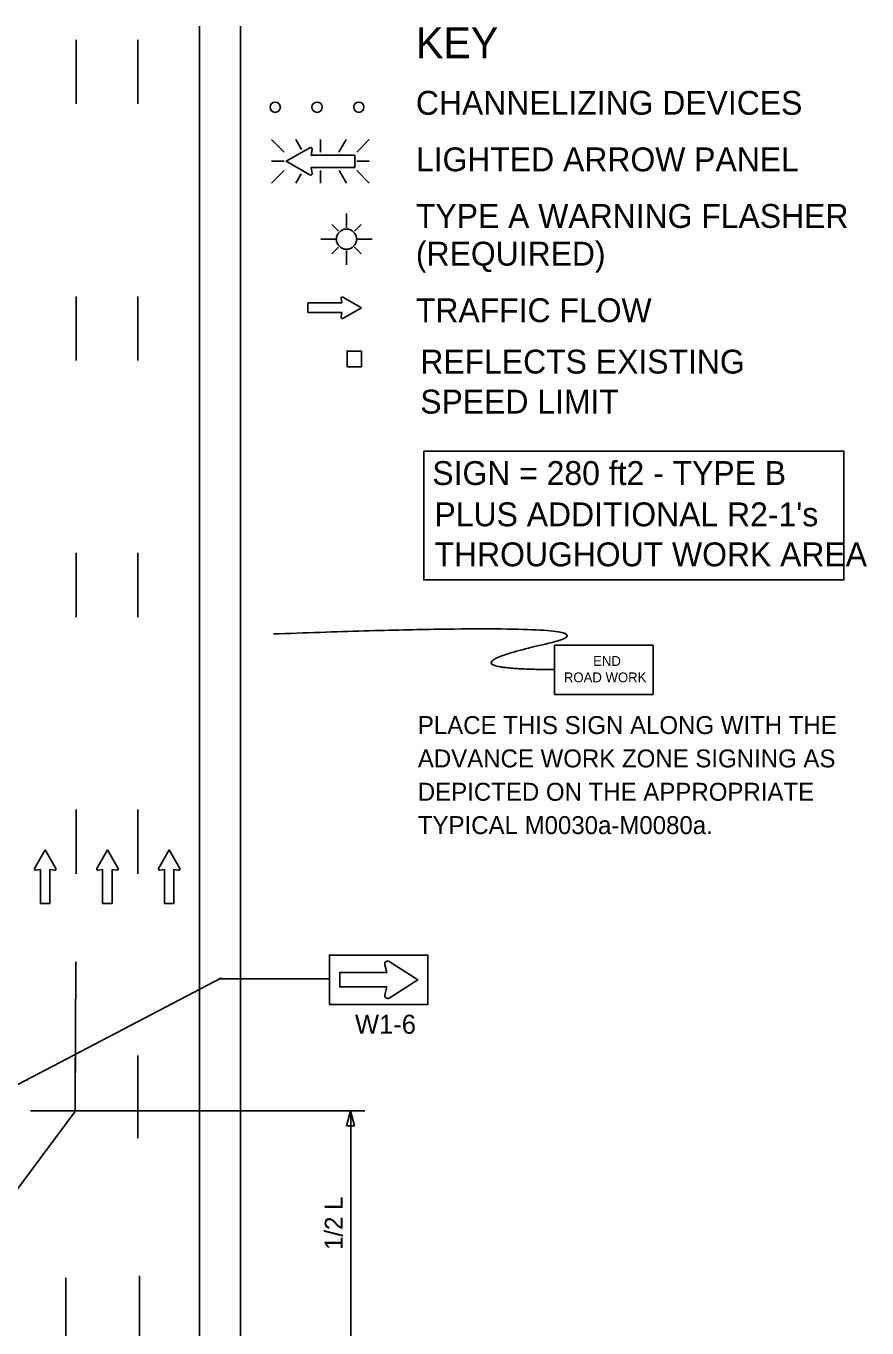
# Model space of a CAD drawing. Extents: x 16038 to 19504, y 5920 to 8321.
# Drawn here: x 17087 to 17415, y 7704 to 8212 of the extents above; entities that cross this region are included whole.
import ezdxf

# ---------------------------------------------------------------- set-up
doc = ezdxf.new("R2010")
doc.units = 0
for name, color, linetype in [('ALI_LEGAL_EX', 7, 'Continuous'), ('MT_SCRATCH_LEVEL_E', 7, 'Continuous'), ('PAVT_EDGE_EX', 7, 'Continuous'), ('TRAFFIC_SIGNS_PR', 7, 'Continuous'), ('TYPICAL_TEXT_DIMEN_EX', 7, 'Continuous'), ('TYPICAL_TEXT_DIMEN_PR', 7, 'Continuous')]:
    doc.layers.add(name, color=color, linetype=linetype)

msp = doc.modelspace()

# ---------------------------------------------------------------- linework, layer by layer
at = {"layer": 'ALI_LEGAL_EX'}
for points in [[(17106.3, 8181.21), (17106.3, 8206.21)], [(17130.3, 8181.21), (17130.3, 8206.21)], [(17106.3, 8081.21), (17106.3, 8106.21)], [(17130.3, 8081.21), (17130.3, 8106.21)], [(17106.3, 7981.21), (17106.3, 8006.21)], [(17130.3, 7981.21), (17130.3, 8006.21)], [(17106.3, 7881.21), (17106.3, 7906.21)], [(17130.3, 7881.21), (17130.3, 7906.21)], [(17130.3, 7778.16), (17130.3, 7810.35)], [(17105.83, 7788.97), (17105.83, 7809.49)], [(17102.22, 7691.46), (17102.22, 7723.64)], [(17130.99, 7692.31), (17130.99, 7724.5)]]:
    msp.add_lwpolyline(points, dxfattribs=at)
at = {"layer": 'MT_SCRATCH_LEVEL_E'}
for p, q in [((17209.56, 8105.43), (17209.88, 8103.65)), ((17209.56, 8105.43), (17209.88, 8103.65)), ((17217.49, 8101.8), (17210.25, 8105.91)), ((17217.49, 8101.8), (17210.25, 8105.91)), ((17209.88, 8103.65), (17196.62, 8103.65)), ((17196.62, 8103.65), (17196.62, 8099.91)), ((17209.88, 8103.65), (17196.62, 8103.65)), ((17196.62, 8103.65), (17196.62, 8099.91)), ((17196.62, 8099.91), (17209.88, 8099.91)), ((17196.62, 8099.91), (17209.88, 8099.91)), ((17209.88, 8099.91), (17209.56, 8098.13)), ((17209.88, 8099.91), (17209.56, 8098.13)), ((17210.25, 8097.65), (17217.49, 8101.8)), ((17210.25, 8097.65), (17217.49, 8101.8)), ((17094.17, 7890.46), (17090.06, 7883.22)), ((17094.17, 7890.46), (17090.06, 7883.22)), ((17098.32, 7883.22), (17094.17, 7890.46)), ((17098.32, 7883.22), (17094.17, 7890.46)), ((17118.44, 7890.46), (17114.33, 7883.22)), ((17118.44, 7890.46), (17114.33, 7883.22)), ((17122.59, 7883.22), (17118.44, 7890.46)), ((17122.59, 7883.22), (17118.44, 7890.46)), ((17142.51, 7890.46), (17138.4, 7883.22)), ((17142.51, 7890.46), (17138.4, 7883.22)), ((17146.66, 7883.22), (17142.51, 7890.46)), ((17146.66, 7883.22), (17142.51, 7890.46)), ((17090.54, 7882.54), (17092.32, 7882.85)), ((17090.54, 7882.54), (17092.32, 7882.85)), ((17092.32, 7882.85), (17092.32, 7869.6)), ((17092.32, 7882.85), (17092.32, 7869.6)), ((17096.06, 7869.6), (17096.06, 7882.85)), ((17096.06, 7882.85), (17097.84, 7882.54)), ((17096.06, 7869.6), (17096.06, 7882.85)), ((17096.06, 7882.85), (17097.84, 7882.54)), ((17114.81, 7882.54), (17116.59, 7882.85)), ((17114.81, 7882.54), (17116.59, 7882.85)), ((17116.59, 7882.85), (17116.59, 7869.6)), ((17116.59, 7882.85), (17116.59, 7869.6)), ((17120.33, 7869.6), (17120.33, 7882.85)), ((17120.33, 7882.85), (17122.11, 7882.54)), ((17120.33, 7869.6), (17120.33, 7882.85)), ((17120.33, 7882.85), (17122.11, 7882.54)), ((17138.88, 7882.54), (17140.66, 7882.85)), ((17138.88, 7882.54), (17140.66, 7882.85)), ((17140.66, 7882.85), (17140.66, 7869.6)), ((17140.66, 7882.85), (17140.66, 7869.6)), ((17144.4, 7869.6), (17144.4, 7882.85)), ((17144.4, 7882.85), (17146.18, 7882.54)), ((17144.4, 7869.6), (17144.4, 7882.85)), ((17144.4, 7882.85), (17146.18, 7882.54)), ((17092.32, 7869.6), (17096.06, 7869.6)), ((17092.32, 7869.6), (17096.06, 7869.6)), ((17116.59, 7869.6), (17120.33, 7869.6)), ((17116.59, 7869.6), (17120.33, 7869.6)), ((17140.66, 7869.6), (17144.4, 7869.6)), ((17140.66, 7869.6), (17144.4, 7869.6))]:
    msp.add_line(p, q, dxfattribs=at)
for centre, start, end in [((17210.02, 8105.5), 60.4248, 189.9638), ((17210.02, 8105.5), 60.4248, 189.9638), ((17210.02, 8098.06), 170.0362, 299.7731), ((17210.02, 8098.06), 170.0362, 299.7731), ((17090.47, 7883), 150.4248, 279.9638), ((17090.47, 7883), 150.4248, 279.9638), ((17097.91, 7883), 260.0362, 29.7731), ((17097.91, 7883), 260.0362, 29.7731), ((17114.74, 7883), 150.4248, 279.9638), ((17114.74, 7883), 150.4248, 279.9638), ((17122.18, 7883), 260.0362, 29.7731), ((17122.18, 7883), 260.0362, 29.7731), ((17138.81, 7883), 150.4248, 279.9638), ((17138.81, 7883), 150.4248, 279.9638), ((17146.25, 7883), 260.0362, 29.7731), ((17146.25, 7883), 260.0362, 29.7731)]:
    msp.add_arc(centre, 0.463, start, end, dxfattribs=at)
at = {"layer": 'PAVT_EDGE_EX'}
for p, q in [((17154.3, 8211.6), (17154.3, 7367.79)), ((17170.3, 8211.6), (17170.3, 7367.79))]:
    msp.add_line(p, q, dxfattribs=at)
at = {"layer": 'TRAFFIC_SIGNS_PR'}
for p, q in [((17182.37, 8167.35), (17187.31, 8162.42)), ((17194.14, 8163.53), (17191.93, 8167.36)), ((17201.46, 8162.42), (17201.46, 8167.36)), ((17208.69, 8162.42), (17211.54, 8167.36)), ((17215.61, 8162.42), (17220.54, 8167.36)), ((17187.31, 8158.87), (17182.37, 8158.87)), ((17182.37, 8150.38), (17187.31, 8155.31)), ((17201.46, 8155.31), (17201.46, 8150.38)), ((17211.59, 8150.38), (17208.74, 8155.31)), ((17215.61, 8158.87), (17220.54, 8158.87)), ((17215.61, 8155.31), (17220.54, 8150.37)), ((17191.89, 8150.38), (17194, 8154.04)), ((17211.64, 8132.95), (17211.64, 8138.58)), ((17208.5, 8131.65), (17205.87, 8134.29)), ((17214.78, 8131.65), (17217.41, 8134.29)), ((17207.7, 8128.52), (17201.66, 8128.52)), ((17208.5, 8125.38), (17205.87, 8122.75)), ((17214.78, 8125.38), (17217.41, 8122.75)), ((17215.58, 8128.52), (17221.67, 8128.52)), ((17211.64, 8118.57), (17211.64, 8124.08)), ((17227.41, 7842.65), (17226.57, 7845.71)), ((17228.25, 7846.95), (17239.41, 7839.85)), ((17162.88, 7840.66), (17010.11, 7760.54)), ((17209.01, 7842.65), (17227.41, 7842.65)), ((17209.01, 7842.65), (17209.01, 7837.05)), ((17227.41, 7837.05), (17209.01, 7837.05)), ((17226.57, 7833.99), (17227.41, 7837.05)), ((17239.41, 7839.85), (17228.25, 7832.75))]:
    msp.add_line(p, q, dxfattribs=at)
for points in [[(17197.38, 8164.14), (17188.09, 8158.87), (17197.39, 8153.54)], [(17198.26, 8154.17), (17197.86, 8156.44), (17214.87, 8156.44), (17214.87, 8161.24), (17197.86, 8161.24), (17198.26, 8163.52)], [(17226.57, 7845.71), (17227.41, 7842.65), (17209.01, 7842.65), (17209.01, 7837.05), (17227.41, 7837.05), (17226.57, 7833.99)], [(17228.25, 7832.75), (17239.41, 7839.85), (17228.25, 7846.95)]]:
    msp.add_lwpolyline(points, dxfattribs=at)
for points in [[(17211.86, 8078.71), (17217.45, 8078.71), (17217.45, 8084.88), (17211.86, 8084.88)], [(17292.78, 7951.07), (17331.18, 7951.07), (17331.18, 7970.27), (17292.78, 7970.27)], [(17205.01, 7830.25), (17243.41, 7830.25), (17243.41, 7849.45), (17205.01, 7849.45)]]:
    msp.add_lwpolyline(points, close=True, dxfattribs=at)
for centre, radius in [((17183.86, 8179.96), 2), ((17200.16, 8179.96), 2), ((17216.46, 8179.96), 2), ((17211.64, 8128.52), 3.94)]:
    msp.add_circle(centre, radius, dxfattribs=at)
for centre, radius, start, end in [((17197.67, 8163.62), 0.598, 350.7308, 118.8916), ((17197.67, 8154.07), 0.597, 241.4833, 9.9593), ((17227.65, 7846.01), 1.12, 57.5304, 195.3269), ((17227.65, 7846.01), 1.12, 57.5304, 195.3269), ((17227.65, 7833.69), 1.12, 164.6731, 302.4696), ((17227.65, 7833.69), 1.12, 164.6731, 302.4696)]:
    msp.add_arc(centre, radius, start, end, dxfattribs=at)
msp.add_open_spline([(17292.94, 7960.79), (17245.7, 7960.79), (17330.72, 7980.14), (17183.14, 7974.65)], degree=2, dxfattribs=at)
at = {"layer": 'TYPICAL_TEXT_DIMEN_EX'}
msp.add_lwpolyline([(17241.75, 8045.95), (17405.55, 8045.95), (17405.55, 7995.69), (17241.75, 7995.69)], close=True, dxfattribs=at)
at = {"layer": 'TYPICAL_TEXT_DIMEN_PR'}
for p, q in [((17105.9, 7789.08), (17106.13, 7846.81)), ((17162.37, 7840.17), (17205.03, 7840.17)), ((17036.11, 7694.87), (17105.73, 7788.44)), ((17218.77, 7788.78), (17088.52, 7788.78)), ((17211.68, 7782.98), (17213.25, 7788.84)), ((17213.25, 7788.84), (17214.82, 7782.98)), ((17213.38, 7695.24), (17213.38, 7788.67)), ((17213.25, 7782.98), (17211.68, 7782.98)), ((17214.82, 7782.98), (17213.25, 7782.98))]:
    msp.add_line(p, q, dxfattribs=at)

# ---------------------------------------------------------------- texts
at = {"layer": 'TRAFFIC_SIGNS_PR'}
for s, height, p in [('END', 3.831, (17307.78, 7962.2)), ('ROAD WORK', 3.831, (17296.39, 7955.82)), ('PLACE THIS SIGN ALONG WITH THE', 7, (17239.45, 7935.63)), ('ADVANCE WORK ZONE SIGNING AS', 7, (17239.45, 7922.63)), ('DEPICTED ON THE APPROPRIATE', 7, (17239.45, 7909.63)), ('TYPICAL M0030a-M0080a.', 7, (17239.45, 7896.63)), ('W1-6', 7.44, (17214.95, 7818.81))]:
    msp.add_text(s, height=height, dxfattribs=at).set_placement(p)
at = {"layer": 'TYPICAL_TEXT_DIMEN_EX'}
for s, height, p in [('KEY', 12, (17238.7, 8199.07)), ('CHANNELIZING DEVICES', 9.3, (17238.7, 8177.02)), ('LIGHTED ARROW PANEL', 9.3, (17238.7, 8154.97)), ('TYPE A WARNING FLASHER', 9.3, (17238.7, 8132.92)), ('(REQUIRED)', 9.3, (17238.7, 8118.22)), ('TRAFFIC FLOW', 9.3, (17238.7, 8096.17)), ('REFLECTS EXISTING', 9.3, (17240.41, 8076.15)), ('SPEED LIMIT', 9.3, (17240.41, 8060.55)), ('SIGN = 280 ft2 - TYPE B', 9.3, (17245.09, 8032.71)), ("PLUS ADDITIONAL R2-1's", 9.3, (17245.96, 8016.62)), ('THROUGHOUT WORK AREA', 9.3, (17245.96, 8001.02))]:
    msp.add_text(s, height=height, dxfattribs=at).set_placement(p)
at = {"layer": 'TYPICAL_TEXT_DIMEN_PR'}
msp.add_text('1/2 L', height=7, rotation=90, dxfattribs=at).set_placement((17210.16, 7734.54))

doc.saveas('drawing.dxf')
